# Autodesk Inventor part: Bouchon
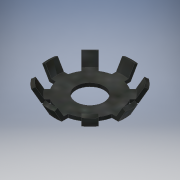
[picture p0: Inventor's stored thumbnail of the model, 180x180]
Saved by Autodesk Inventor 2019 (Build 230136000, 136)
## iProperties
Created: 2018-06
Part Number: Bouchon
Material: Acier
Document SubType Name: Modeling
Designer: Fabian Perrée
Density: 7.85 g/cm^3
Appearance: Plaque
Author: Fabian Perrée
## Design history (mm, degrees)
sketch "Esquisse1"
  geometry: L1 (0, 0)-(0, 2); L2 (2, 0)-(4.99, 0); L3 (4.99, 0)-(6, 1.75); L4 (6, 1.75)-(5.567, 2); L5 (5.567, 2)-(4.701, 0.5); L6 (4.701, 0.5)-(2, 0.5); L7 (2, 0.5)-(2, 0)
  constraints: 14 end point, 3 perpendicular, 1 equal length, 1 horizontal, 1 horizontal alignment, 1 parallel, 1 point on line, 1 vertical
  dimensions: "d0" = 4 diameter of L7 L1; "d1" = 60 deg angle of L2 L3; "d2" = 1.75 distance from line of L2 L3.end; "d3" = 12 diameter of L3.end L1; "d4" = 0.5 distance of L3.end L4.end
revolve "Révolution1" sketch "Esquisse1" stored, may be unused: angle "d5" = 90 deg
sketch "Esquisse2"
  geometry: L1 (-6, -0.875)-(-4, -0.875); L2 (-4, -0.875)-(-4, 0.875); L3 (-4, 0.875)-(-6, 0.875); L4 (-6, 0.875)-(-6, -0.875); L5 (-6, 0)-(0, 0); L6 (-3.624, -4.861)-(-2.21, -3.447); L7 (-2.21, -3.447)-(-3.447, -2.21); L8 (-3.447, -2.21)-(-4.861, -3.624); L9 (-4.861, -3.624)-(-3.624, -4.861); L10 (0.875, -6)-(0.875, -4); L11 (0.875, -4)-(-0.875, -4); L12 (-0.875, -4)-(-0.875, -6); L13 (-0.875, -6)-(0.875, -6); L14 (4.861, -3.624)-(3.447, -2.21); L15 (3.447, -2.21)-(2.21, -3.447); L16 (2.21, -3.447)-(3.624, -4.861); L17 (3.624, -4.861)-(4.861, -3.624); L18 (6, 0.875)-(4, 0.875); L19 (4, 0.875)-(4, -0.875); L20 (4, -0.875)-(6, -0.875); L21 (6, -0.875)-(6, 0.875); L22 (3.624, 4.861)-(2.21, 3.447); L23 (2.21, 3.447)-(3.447, 2.21); L24 (3.447, 2.21)-(4.861, 3.624); L25 (4.861, 3.624)-(3.624, 4.861); L26 (-0.875, 6)-(-0.875, 4); L27 (-0.875, 4)-(0.875, 4); L28 (0.875, 4)-(0.875, 6); L29 (0.875, 6)-(-0.875, 6); L30 (-4.861, 3.624)-(-3.447, 2.21); L31 (-3.447, 2.21)-(-2.21, 3.447); L32 (-2.21, 3.447)-(-3.624, 4.861); L33 (-3.624, 4.861)-(-4.861, 3.624); C1 r 2 at (0, 0) reference; A1 r 4.095 centre (0, 0) between (-2.21, -3.447) and (-0.875, -4); A2 r 4.095 centre (0, 0) between (0.875, -4) and (2.21, -3.447); A3 r 4.095 centre (0, 0) between (3.447, -2.21) and (4, -0.875); A4 r 4.095 centre (0, 0) between (4, 0.875) and (3.447, 2.21); A5 r 4.095 centre (0, 0) between (2.21, 3.447) and (0.875, 4); A6 r 4.095 centre (0, 0) between (-0.875, 4) and (-2.21, 3.447); A7 r 4.095 centre (0, 0) between (-3.447, 2.21) and (-4, 0.875); A8 r 4.095 centre (0, 0) between (-4, -0.875) and (-3.447, -2.21); 7 further points
  constraints: 66 end point, 16 point on circle, 8 centre point, 8 midpoint, 2 parallel, 2 perpendicular, 1 coincident, 1 horizontal, 1 horizontal alignment, 1 vertical, 75 other
  dimensions: "d6" = 1.75 distance of L3.end L1.start; "d7" = 4 distance from line of C1.centre L2; "d10" = 360 deg dimension on C1.centre L1.start (derived)
extrude "Extrusion1" sketch "Esquisse2" extent not by distance; stored distance "d12" = 0; taper "d13" = 0 deg
node "Solide1"
